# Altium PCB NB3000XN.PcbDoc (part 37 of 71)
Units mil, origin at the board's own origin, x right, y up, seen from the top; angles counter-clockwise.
Board outline 9527.56 x 6929.77 mil, 6 copper layers (Top Layer, GND+SHIELD, MidLayer1, MidLayer2, P2 - 3V3+5V0, Bottom Layer), stack 62.375 mil thick; 832 components, 1027 nets, 4655 pads, 4981 vias.
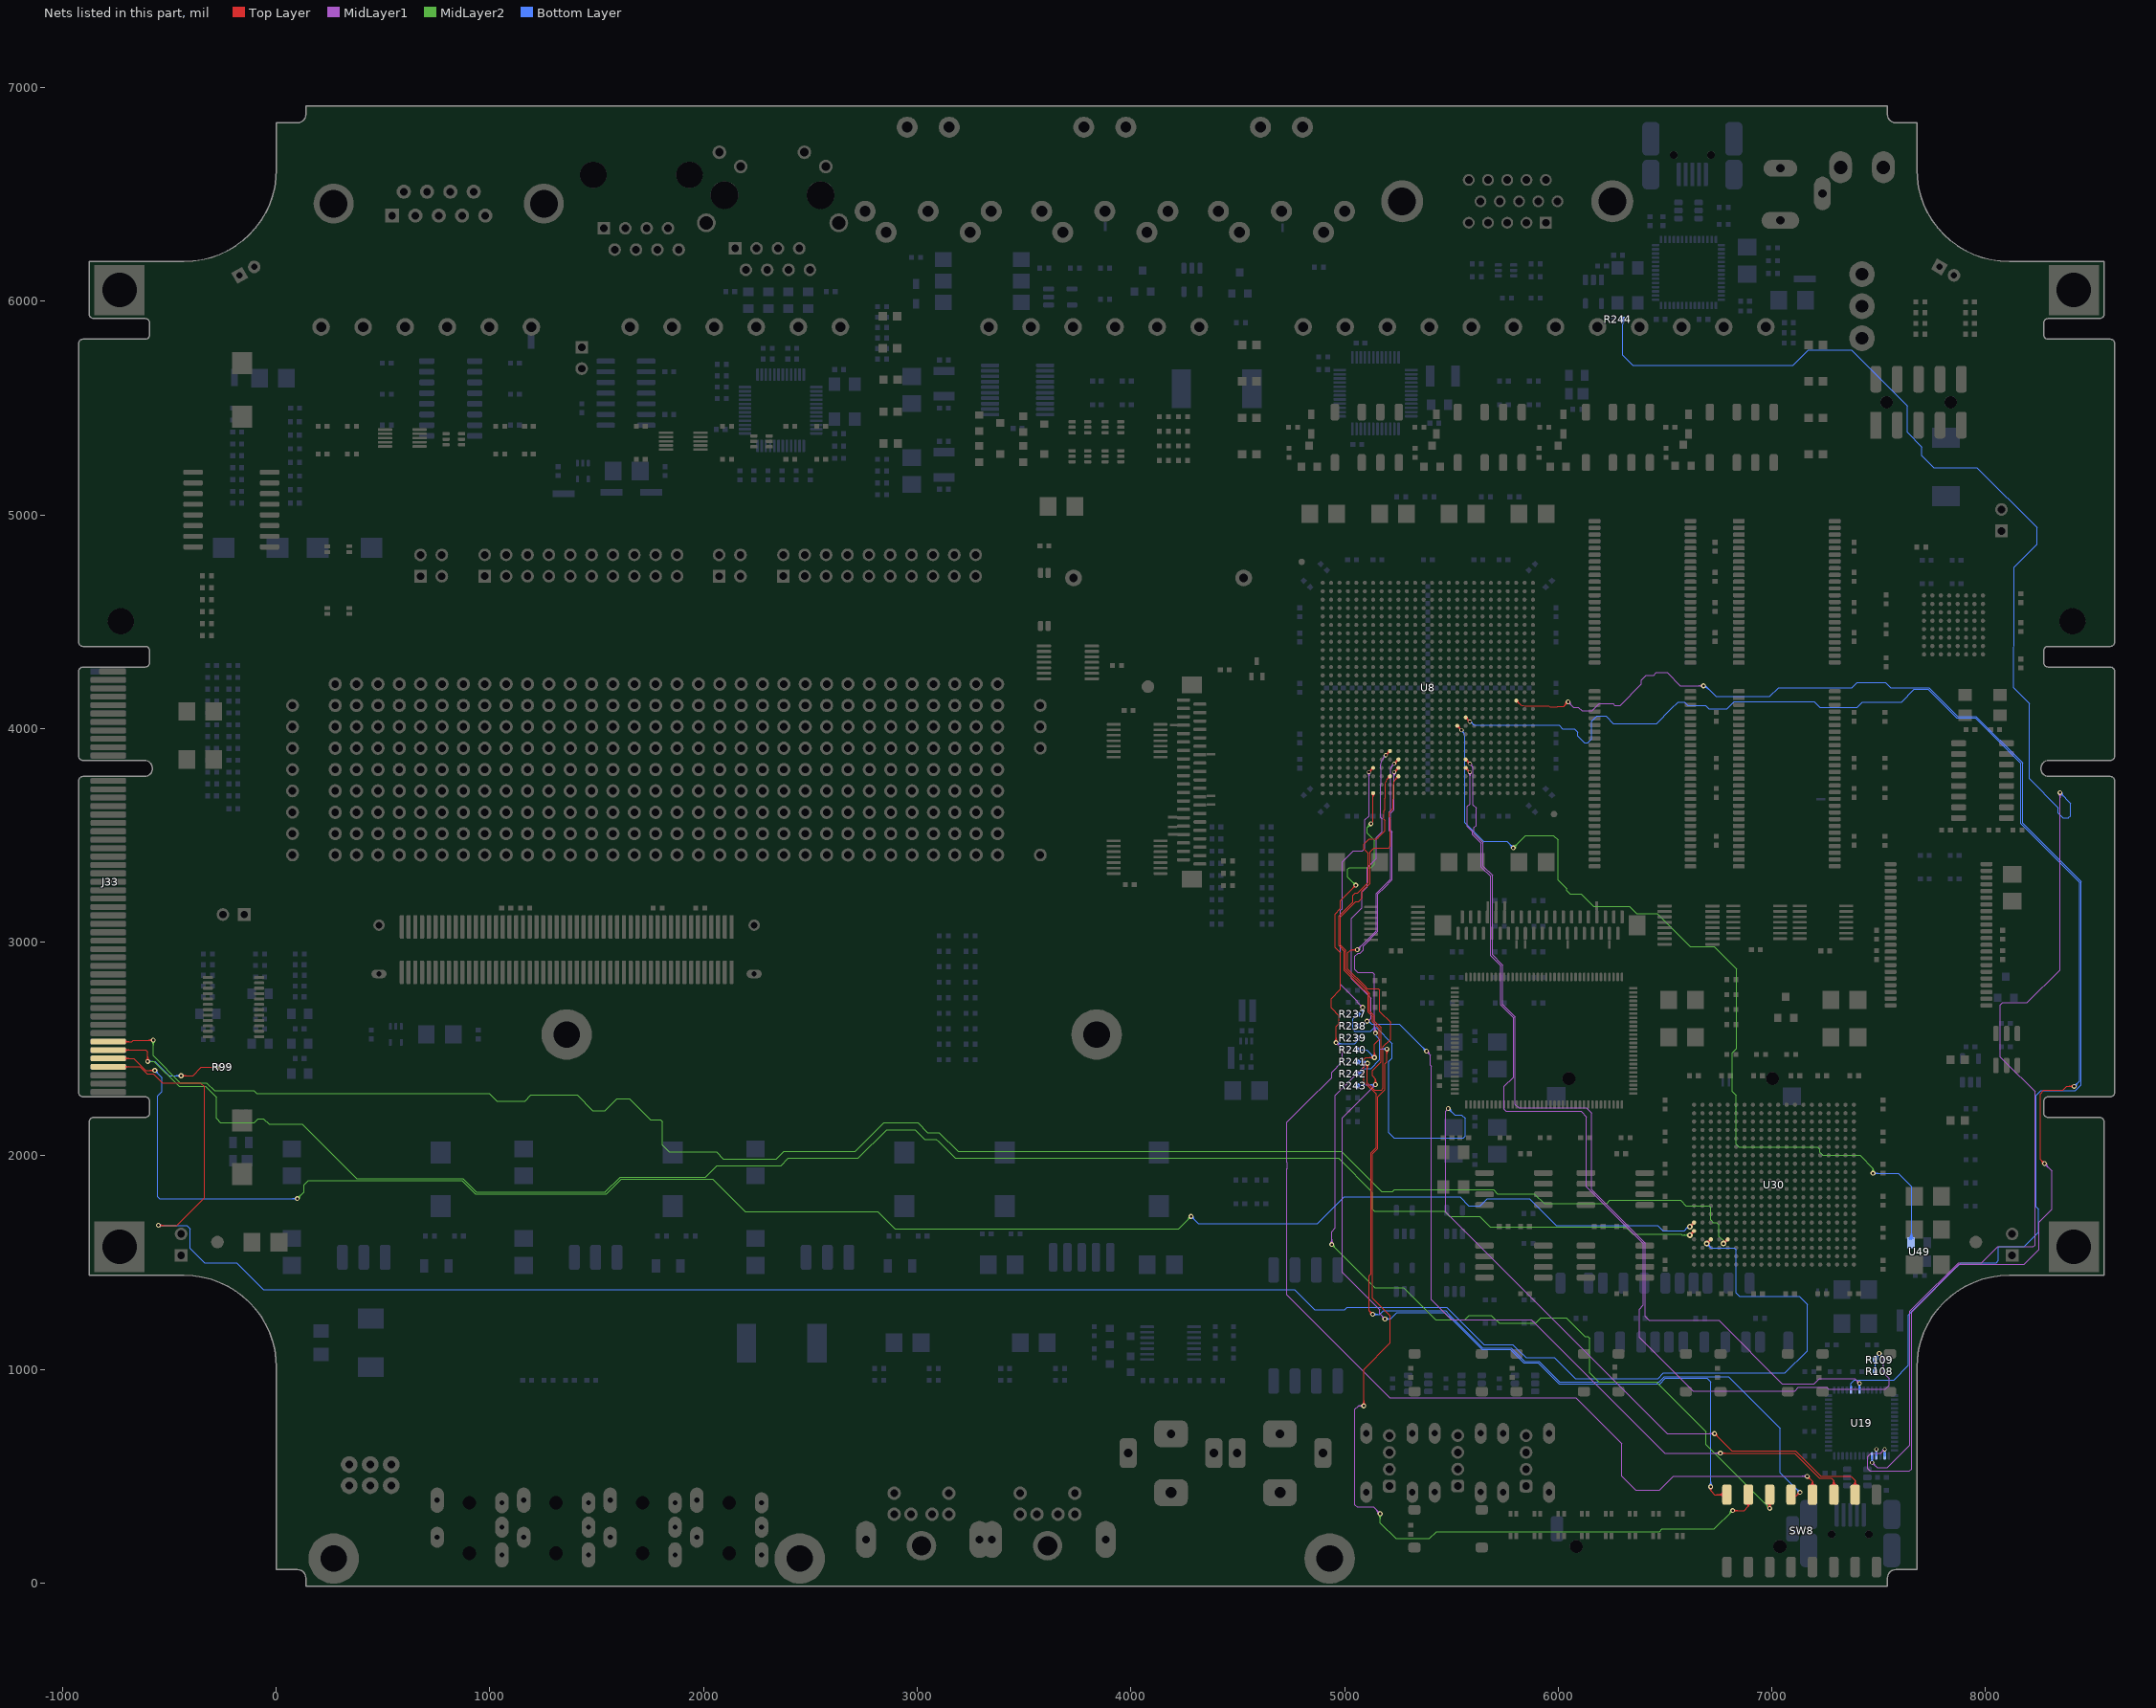
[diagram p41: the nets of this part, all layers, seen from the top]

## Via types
v1: diameter 23, hole 11.81, Top Layer to Bottom Layer, 3672 vias
v2: diameter 26, hole 11.81, Top Layer to Bottom Layer, 461 vias
v3: diameter 19, hole 11.81, Top Layer to Bottom Layer, tented both sides, 396 vias
v4: diameter 23.62, hole 11.81, Top Layer to Bottom Layer, 288 vias
v5: diameter 20, hole 11.81, Top Layer to Bottom Layer, 91 vias
v6: diameter 23, hole 11.81, Top Layer to Bottom Layer, tented both sides, 50 vias
v7: diameter 31, hole 11.81, Top Layer to Bottom Layer, 15 vias
v8: diameter 27.56, hole 11.81, Top Layer to Bottom Layer, tented both sides, 4 vias
v9: diameter 29, hole 11.81, Top Layer to Bottom Layer, 3 vias
v10: diameter 21, hole 11.81, Top Layer to Bottom Layer, 1 vias

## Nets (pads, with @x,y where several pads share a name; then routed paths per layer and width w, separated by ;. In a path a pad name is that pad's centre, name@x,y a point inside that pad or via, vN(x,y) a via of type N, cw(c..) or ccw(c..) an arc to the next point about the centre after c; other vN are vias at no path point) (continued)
DBUSB.READY: U8.R24 U19.33 | length 6898
  Top Layer w4: U8.R24@5803.39,4123.6 cw(c5803.39,4105.88) 5815.92,4118.41 ; U8.R24@5810.73,4130.94 ccw(c5828.45,4130.94) 5815.92,4118.41 ; v1@6036.69,4125.04 cw(c6013.76,4125.04) 6029.97,4108.82 cw(c6046.19,4092.61) v1@6046.19,4115.54 ; v1@6037.01,4125.04 v1(6046.19,4125.04) 6026,4104.85 5997.48,4104.85 5994.33,4101.71 5960.72,4101.71 5955.35,4107.08 5924.74,4107.08 5920,4107.08 5910,4107.08 5843.27,4107.08 cw(c5843.27,4145.76) 5815.92,4118.41 ; v1@6040.69,4125.04 cw(c6027.41,4125.04) 6036.8,4115.65 cw(c6046.19,4106.26) v1@6046.19,4119.54
  MidLayer1 w4: v1@6046.19,4115.54 cw(c6046.19,4092.61) 6062.41,4108.82 cw(c6078.63,4125.04) v1@6055.69,4125.04 ; v1@6046.19,4119.54 cw(c6046.19,4106.26) 6055.58,4115.65 cw(c6064.97,4125.04) v1@6051.69,4125.04 ; v1(6046.19,4125.04) 6071.23,4100 6095,4100 6111.63,4083.37 6159.23,4083.37 6192.56,4116.71 6256.86,4116.71 6265.19,4108.37 6290.19,4108.37 6390.19,4208.37 6390.19,4228.02 6412.21,4250.04 6447.67,4250.04 6459.34,4261.71 6509.52,4261.71 6571.19,4200.04 v1(6680.19,4200.04) ; v1@6673.47,4193.32 ccw(c6657.26,4177.11) 6657.26,4200.04 ccw(c6657.26,4222.98) v1@6673.47,4206.76 ; v1@6676.3,4196.15 ccw(c6666.91,4186.76) 6666.91,4200.04 ccw(c6666.91,4213.32) v1@6676.3,4203.93
  Bottom Layer w4: v1@6680.19,4190.54 cw(c6680.19,4146.68) 6711.2,4177.69 ; v1@6680.19,4194.54 cw(c6680.19,4160.34) 6704.37,4184.52 ; v1@6680.19,4198.54 cw(c6680.19,4174) 6697.55,4191.35 ; v1(6680.19,4200.04) 6688.86,4200.04 6738.86,4150.04 6990.19,4150.04 7032.19,4192.04 7374.19,4192.04 7398.52,4216.37 7430,4216.37 7444.19,4216.37 7532.35,4216.37 7557.02,4191.71 7575,4191.71 7734.84,4191.71 7868.84,4057.71 7955.15,4057.71 8173.52,3839.34 8173.52,3557.79 8448,3283.31 8448,2333.25 8420.68,2305.94 8260.38,2305.94 8238,2283.56 8238,1760.5 8248.36,1750.14 ; U19.33@7367.96,918.09 ccw(c7361.13,924.92) 7370.79,924.92 ccw(c7380.44,924.92) U19.33@7373.62,918.09 ; U19.33@7370.79,904.33 7370.79,935.66 7386.84,951.71 7571.71,951.71 7640,1020 7640,1255.2 7843.17,1458.37 ; 7843.37,1458.37 7885.37,1500.37 8050.37,1500.37 8060,1510 8060,1570 8065,1575 8180,1575 8248.36,1643.36 8248.36,1750.14 ; 8239.19,1759.31 8248.36,1750.14
DBUSB.RESET_N: U8.V17 U49.3 | length 4668.6
  Top Layer w4: U8.V17@5527.8,4005.33 cw(c5527.8,3987.23) 5540.6,4000.03 cw(c5553.4,4012.83) U8.V17@5535.3,4012.83 ; U8.V17@5527.8,4005.49 cw(c5527.8,3987.77) 5540.33,4000.3 cw(c5552.86,4012.83) U8.V17@5535.14,4012.83 ; U8.V17@5527.8,4012.83 v3(5547.48,3993.15) ; 5534.68,4005.95 cw(c5521.87,3993.15) 5539.98,3993.15 ccw(c5521.87,3993.15) 5534.68,4005.95 ; 5534.68,4005.95 ccw(c5547.48,4018.76) 5547.48,4000.65 cw(c5547.48,4018.76) 5534.68,4005.95
  MidLayer2 w4: v1(5790.19,3441.71) 5848.52,3500.04 5978.17,3500.04 5998.86,3479.35 5998.86,3290.95 6012.62,3277.19 6012.71,3277.19 6040.19,3249.71 6040.19,3241.71 6056.86,3225.04 6106.86,3225.04 6165.19,3166.71 6333.52,3166.71 6366.86,3133.37 6462.52,3133.37 6616.86,2979.04 6729.84,2979.04 6835.52,2873.35 6835.52,2503.71 6815.19,2483.37 6815.19,2300.37 6832.19,2283.37 6832.19,2099.96 ; v1@5790.19,3447.21 ccw(c5790.19,3460.49) 5799.58,3451.1 ccw(c5808.97,3441.71) v1@5795.69,3441.71 ; v1@5790.19,3451.21 ccw(c5790.19,3474.14) 5806.41,3457.93 ccw(c5822.63,3441.71) v1@5799.69,3441.71 ; 6832.15,2100 6832.19,2099.96 ; v1@7467.01,1925.62 ccw(c7452.8,1940.71) 7473.52,1940.71 ; v1@7469.75,1922.71 ccw(c7461.53,1931.44) 7473.52,1931.44 ccw(c7485.52,1931.44) v1@7477.3,1922.71 ; v1(7473.52,1918.71) 7473.52,1940.71 ; v1@7480.04,1925.62 cw(c7494.25,1940.71) 7473.52,1940.71 ; 6832.19,2099.96 6833.52,2098.63 6833.52,2053.98 6846.02,2041.48 7214.72,2041.48 7225.85,2030.35 7225.85,2015.98 7238.35,2003.48 7338.89,2003.48 7340,2002.37 7411.86,2002.37 7473.52,1940.71
  Bottom Layer w4: v3@5546.18,3985.76 cw(c5543.03,3967.93) 5557.87,3978.32 cw(c5572.7,3988.7) v3@5554.87,3991.85 ; 5557.9,3978.29 cw(c5529.86,3960.64) 5562.99,3960.47 5562.99,3876.1 5562.99,3670 5562.99,3660 5562.99,3558.91 5573.65,3548.24 5650.19,3471.71 5760.19,3471.71 v1(5790.19,3441.71) ; v1@5780.69,3441.71 ccw(c5757.76,3441.71) 5773.97,3457.93 ccw(c5790.19,3474.14) v1@5790.19,3451.21 ; v1@5784.69,3441.71 ccw(c5771.41,3441.71) 5780.8,3451.1 ccw(c5790.19,3460.49) v1@5790.19,3447.21 ; v1(7473.52,1918.71) 7591.29,1918.71 7655,1855 U49.3@7655,1607 ; v1@7477.41,1914.82 cw(c7486.8,1905.43) 7486.8,1918.71 cw(c7486.8,1931.99) v1@7477.41,1922.6 ; v1@7480.24,1911.99 cw(c7496.46,1895.77) 7496.46,1918.71 cw(c7496.46,1941.64) v1@7480.24,1925.43 ; U49.3@7641.03,1613.28 ccw(c7607.31,1647) 7655,1647 ; U49.3@7643.86,1610.45 ccw(c7616.97,1637.34) 7655,1637.34 ; U49.3@7646.69,1607.62 ccw(c7626.63,1627.69) 7655,1627.69 ; 7655,1623.56 ccw(c7673.54,1623.56) U49.3@7660.43,1610.45 ; 7655,1633.22 ccw(c7683.2,1633.22) U49.3@7663.26,1613.28
DBUSB.SLOE: U8.AB18 U19.35 | length 4508.8
  Top Layer w4: U8.AB18@5567.17,3847.85 cw(c5567.17,3829.75) 5579.97,3842.55 cw(c5592.77,3855.35) U8.AB18@5574.67,3855.35 ; U8.AB18@5567.17,3848.01 cw(c5567.17,3830.29) 5579.7,3842.82 cw(c5592.23,3855.35) U8.AB18@5574.51,3855.35 ; U8.AB18@5567.17,3855.35 v3(5586.85,3835.67) ; 5574.05,3848.47 cw(c5561.24,3835.67) 5579.35,3835.67 ccw(c5561.24,3835.67) 5574.05,3848.47 ; 5574.05,3848.47 ccw(c5586.85,3861.28) 5586.85,3843.17 cw(c5586.85,3861.28) 5574.05,3848.47
  MidLayer1 w4: v3@5586.2,3828.2 cw(c5584.62,3810.16) 5598.49,3821.8 cw(c5612.36,3833.44) v3@5594.32,3835.02 ; 5598.24,3822.09 cw(c5588.31,3812.16) 5602.36,3812.16 5602.36,3718.62 5602.36,3670 5602.36,3660 5602.36,3642.64 5616.19,3628.81 5616.19,3545.69 5606.86,3536.35 5606.86,3508.04 5648.52,3466.37 5648.52,3356.68 5692.19,3313.02 5692.19,2940.98 5730.85,2902.32 5740.19,2892.98 5740.19,2708.37 5798.52,2650.04 5798.52,2241.71 5815.19,2225.04 6131.86,2225.04 6156.86,2200.04 6156.86,1841.71 6406.81,1591.75 6406.81,1248.19 6425,1230 6751.9,1230 7048.52,933.37 7198.52,933.37 7223.52,958.37 7387.44,958.37 v5(7410.16,935.66) ; v5@7402.16,935.66 ccw(c7382.84,935.66) 7396.5,949.32 ccw(c7410.16,962.98) v5@7410.16,943.66
  Bottom Layer w8: v5@7405.91,931.42 cw(c7395.67,921.18) 7410.16,921.18 cw(c7424.64,921.18) v5@7414.4,931.42 ; U19.35@7410.16,904.33 v5(7410.16,935.66)
DBUSB.VBUS: R108.1 R109.1 U8.AC18 | length 5262
  Top Layer w4: U8.AC18@5567.17,3808.48 cw(c5567.17,3790.38) 5579.97,3803.18 cw(c5592.77,3815.98) U8.AC18@5574.67,3815.98 ; U8.AC18@5567.17,3808.64 cw(c5567.17,3790.92) 5579.7,3803.45 cw(c5592.23,3815.98) U8.AC18@5574.51,3815.98 ; U8.AC18@5567.17,3815.98 v3(5586.85,3796.3) ; 5574.05,3809.1 cw(c5561.24,3796.3) 5579.35,3796.3 ccw(c5561.24,3796.3) 5574.05,3809.1 ; 5574.05,3809.1 ccw(c5586.85,3821.91) 5586.85,3803.8 cw(c5586.85,3821.91) 5574.05,3809.1
  MidLayer1 w4: v3@5581.55,3791 cw(c5568.74,3778.19) 5586.85,3778.19 cw(c5604.96,3778.19) v3@5592.15,3791 ; v3@5581.66,3791.11 cw(c5569.12,3778.57) 5586.85,3778.57 cw(c5604.58,3778.57) v3@5592.04,3791.11 ; v3(5586.85,3796.3) 5586.85,3718.62 5586.85,3670 5586.85,3660 5586.85,3646.66 5575.19,3635 5575.19,3541.12 5598.86,3517.46 5598.86,3504.71 5612.27,3491.29 5640.19,3463.37 5640.19,3352.37 5684.19,3308.37 5684.19,2937.67 5731.86,2890 5731.86,2705.39 5790.52,2646.73 5790.52,2368.02 5747.5,2325 5747.5,2217.73 5756.86,2208.37 6106.86,2208.37 6131.86,2183.37 6131.86,1855.39 6377.04,1610.21 6398.81,1588.44 6398.81,1301.18 6380.52,1282.9 6380.52,1149.61 6630.43,899.71 7108,899.71 7125,916.71 7256.86,916.71 7265.19,908.37 7531.86,908.37 7548.52,925.04 7548.52,958.37 7523.52,983.37 7523.52,1054.04 v1(7502.52,1075.04) ; v1@7502.52,1065.54 cw(c7502.52,1042.61) 7518.74,1058.82 cw(c7534.96,1075.04) v1@7512.02,1075.04 ; v1@7502.52,1069.54 cw(c7502.52,1056.26) 7511.91,1065.65 cw(c7521.3,1075.04) v1@7508.02,1075.04
  Bottom Layer w4: R108.1@7477.23,997.08 ccw(c7461.32,1012.99) 7483.82,1012.99 ccw(c7506.32,1012.99) R108.1@7490.41,997.08 ; R109.1@7477.23,1037.92 cw(c7461.32,1022.01) 7483.82,1022.01 cw(c7506.32,1022.01) R109.1@7490.41,1037.92 ; R108.1@7480.06,994.25 ccw(c7470.98,1003.33) 7483.82,1003.33 ccw(c7496.66,1003.33) R108.1@7487.58,994.25 ; R109.1@7480.06,1040.75 cw(c7470.98,1031.67) 7483.82,1031.67 cw(c7496.66,1031.67) R109.1@7487.58,1040.75 ; R108.1@7483.82,990 R109.1@7483.82,1041.71 ; R109.1@7483.82,1045 R109.1@7483.82,1041.71 ; R109.1@7485.14,1045.57 cw(c7501.49,1046.51) 7489.91,1058.09 ; R109.1@7489.13,1045.8 cw(c7513.42,1047.2) 7496.21,1064.4 ; 7492.36,1060.54 ccw(c7486.07,1066.83) v1@7494.02,1070.8 ; R109.1@7493.12,1046.03 cw(c7525.35,1047.88) v1@7502.52,1070.71 ; 7493.7,1061.89 cw(c7502.52,1053.07) v1@7502.52,1065.54 ; 7496.28,1064.47 ccw(c7491.31,1069.44) v1@7497.6,1072.58 ; v1(7502.52,1075.04) v1@7502.52,1070.71 ; R109.1@7483.82,1041.71 7485.47,1043.35 7490.19,1048.08 7490.19,1058.37 v1@7502.52,1070.71 ; R109.1@7483.82,1054.81 ccw(c7483.82,1061.59) 7488.61,1056.8 cw(c7483.82,1061.59) R109.1@7483.82,1054.81
DBUSB.WR_N: U8.U18 U19.2 | length 7864.3
  Top Layer w4: U8.U18@5567.17,4044.7 cw(c5567.17,4026.6) 5579.97,4039.4 cw(c5592.77,4052.2) U8.U18@5574.67,4052.2 ; U8.U18@5567.17,4044.86 cw(c5567.17,4027.14) 5579.7,4039.67 cw(c5592.23,4052.2) U8.U18@5574.51,4052.2 ; U8.U18@5567.17,4052.2 v3(5586.85,4032.52) ; v1@8266.73,1964 ccw(c8243.8,1964) 8260.02,1980.22 ccw(c8276.23,1996.43) v1@8276.23,1973.5 ; v1@8270.73,1964 ccw(c8257.46,1964) 8266.85,1973.39 ccw(c8276.23,1982.78) v1@8276.23,1969.5 ; v1(8276.23,1964) 8256.86,1983.37 8256.86,2290.54 8273.31,2307 8362,2307 8380.04,2325.04 8414.96,2325.04 v1(8415,2325) ; 8391.97,2325.04 cw(c8391.97,2301.97) v1@8408.28,2318.28 ; 8392.16,2325.04 ccw(c8392.16,2347.84) v1@8408.28,2331.72 ; 8401.62,2325.04 cw(c8401.62,2311.62) v1@8411.11,2321.11 ; 8401.82,2325.04 ccw(c8401.82,2338.18) v1@8411.11,2328.89 ; 5574.05,4045.32 cw(c5561.24,4032.52) 5579.35,4032.52 ccw(c5561.24,4032.52) 5574.05,4045.32 ; 5574.05,4045.32 ccw(c5586.85,4058.13) 5586.85,4040.02 cw(c5586.85,4058.13) 5574.05,4045.32
  MidLayer1 w4: v5@7520.27,627 cw(c7500.95,627) 7514.61,613.34 cw(c7528.27,599.69) v5@7528.27,619 ; v5(7528.27,627) 7509.64,608.37 7465.19,608.37 7448.52,591.71 7448.52,536.48 7460,525 7644.38,525 7654.02,534.64 7654.02,1269.23 7876.51,1491.71 8180,1491.71 8250,1561.71 8250,1690 8310,1750 8310,1930.23 v1(8276.23,1964) v1@8276.11,1964.12 ; v1@8276.23,1954.5 cw(c8276.23,1931.56) 8292.45,1947.78 cw(c8308.67,1964) v1@8285.73,1964 ; v1@8276.23,1958.5 cw(c8276.23,1945.22) 8285.62,1954.61 cw(c8295.01,1964) v1@8281.73,1964
  Bottom Layer w4: v3@5587.5,4025.05 cw(c5589.08,4007.01) 5600.72,4020.88 cw(c5612.36,4034.75) v3@5594.32,4033.17 ; 5600.43,4021.13 ccw(c5610.36,4031.06) 5610.36,4017.01 5703.9,4017.01 5910,4017.01 5920,4017.01 5924.74,4017.01 5928.74,4017.01 5928.74,4016.71 6003.86,4016.71 6021.06,3999.5 6075.25,3999.5 6092.5,3982.25 6092.5,3963.98 6123.12,3933.37 6137.61,3933.37 6156.86,3952.61 6156.86,4033.37 6181.86,4058.37 6223.52,4058.37 6257.69,4024.21 6460.77,4024.21 6528.19,4091.63 6528.19,4091.71 6561.52,4125.04 6590.19,4125.04 6606.86,4108.37 6688.86,4108.37 6705.52,4091.71 6790,4091.71 6824.33,4126.04 7198.96,4126.04 7224.96,4100.04 7398.52,4100.04 7423.52,4125.04 7606.67,4125.04 7665,4183.37 7731.86,4183.37 7865.52,4049.71 7951.84,4049.71 8165.19,3836.36 8165.19,3554.81 8440,3280 8440,2350 v1(8415,2325) ; v1@8415,2330.5 ccw(c8415,2343.78) 8424.39,2334.39 ccw(c8433.78,2325) v1@8420.5,2325 ; v1@8415,2334.5 ccw(c8415,2357.43) 8431.22,2341.22 ccw(c8447.44,2325) v1@8424.5,2325
  Bottom Layer w8: v5@7524.03,622.76 cw(c7513.78,612.51) 7528.27,612.51 cw(c7542.75,612.51) v5@7532.51,622.76 ; U19.2@7528.27,595.67 v5(7528.27,627)
DBUSB.XTALIN: R244.1 U19.5 | length 8457.5
  MidLayer1 w4: v5@7469.21,556.34 cw(c7469.21,537.02) 7482.87,550.68 cw(c7496.53,564.34) v5@7477.21,564.34 ; v5(7469.21,564.34) 7493.55,540 7540,540 7646.02,646.02 7646.02,1272.54 7677.84,1304.35 7873.52,1500.04 7981.86,1500.04 8056.86,1575.04 8224.19,1575.04 8231.86,1582.71 8231.86,2300.04 8094.47,2437.43 8070,2461.9 8070,2706.71 8080,2716.71 8195.23,2716.71 8348.52,2870 v1(8348.52,3700.04) ; v1@8341.81,3693.32 cw(c8325.59,3677.11) 8348.52,3677.11 cw(c8371.46,3677.11) v1@8355.24,3693.32 ; v1@8344.64,3696.15 cw(c8335.25,3686.76) 8348.52,3686.76 cw(c8361.8,3686.76) v1@8352.41,3696.15
  Bottom Layer w4: R244.1@6294.59,5907.92 cw(c6278.68,5892.01) 6301.18,5892.01 cw(c6323.68,5892.01) R244.1@6307.77,5907.92 ; R244.1@6297.42,5910.75 cw(c6288.34,5901.67) 6301.18,5901.67 cw(c6314.02,5901.67) R244.1@6304.94,5910.75 ; R244.1@6301.18,5915 6301.18,5747.38 6348.52,5700.04 7098.52,5700.04 7170.48,5772 7372.36,5772 7633.75,5510.61 7633.75,5386.25 7701.98,5318.02 7701.98,5278.02 7758.88,5221.12 7960.17,5221.12 8240.69,4940.6 8240.69,4862 8135,4756.31 8135,4385 8131.86,4381.86 8131.86,4191.37 8206.52,4116.71 8206.52,3764.53 8341.06,3630 8341.06,3603.94 8362.13,3582.87 8389.69,3582.87 8390.19,3583.37 8398.52,3591.71 8399.02,3592.21 8399.02,3649.54 v1(8348.52,3700.04) ; v1@8348.52,3690.54 cw(c8348.52,3667.61) 8364.74,3683.82 cw(c8380.96,3700.04) v1@8358.02,3700.04 ; v1@8348.52,3694.54 cw(c8348.52,3681.26) 8357.91,3690.65 cw(c8367.3,3700.04) v1@8354.02,3700.04
  Bottom Layer w8: v5@7464.97,568.58 ccw(c7454.73,578.82) 7469.21,578.82 ccw(c7483.7,578.82) v5@7473.46,568.58 ; v5(7469.21,564.34) U19.5@7469.21,595.67
DBUSB.XTALOUT: U19.4 | length 54.1
  Bottom Layer w8: v5@7484.65,622.76 cw(c7474.41,612.51) 7488.9,612.51 cw(c7503.38,612.51) v5@7493.14,622.76 ; U19.4@7488.9,595.67 v5(7488.9,627)
DIAGCOMMS.DIN: J33.A46 U30.V17 | length 10672.3
  Top Layer w4: J33.A46@-785.98,2416.64 -637.72,2416.64 -605.08,2384 -575.14,2384 -533.18,2342.04 -354.79,2342.04 -335.52,2322.77 -335.52,1804.48 -464.96,1675.04 v1(-551.48,1675.04) ; J33.A46@-711.58,2411.14 cw(c-698.3,2397.86) -698.3,2416.64 cw(c-698.3,2435.42) J33.A46@-711.58,2422.14 ; J33.A46@-708.76,2408.31 cw(c-688.65,2388.2) -688.65,2416.64 cw(c-688.65,2445.08) J33.A46@-708.76,2424.97 ; v1@-547.59,1671.15 cw(c-538.2,1661.76) -538.2,1675.04 cw(c-538.2,1688.32) v1@-547.59,1678.93 ; v1@-544.76,1668.32 cw(c-528.54,1652.11) -528.54,1675.04 cw(c-528.54,1697.98) v1@-544.76,1681.76
  Top Layer w8: v2(6695.04,1589.41) U30.V17@6714.72,1609.09 ; v2@6695.04,1598.41 ccw(c6695.04,1620.14) 6710.4,1604.77 ccw(c6725.77,1589.41) v2@6704.04,1589.41 ; U30.V17@6708.88,1609.09 cw(c6694.78,1609.09) 6704.75,1599.12 cw(c6714.72,1589.15) U30.V17@6714.72,1603.25
  Bottom Layer w4: v1(-551.48,1675.04) -418.14,1675.04 -401.48,1658.37 -401.48,1566.71 -334.81,1500.04 -184.81,1500.04 -59.81,1375.04 4765.19,1375.04 4860.23,1280 5000,1280 5011.71,1291.71 5478.88,1291.71 5653.58,1117 5786.92,1117 5813.92,1090 5842.12,1061.8 5848.92,1055 5982.88,1055 6079.5,958.37 6466.84,958.37 6491.84,983.37 7062.06,983.37 7165.52,1086.84 7165.52,1304.48 7128.29,1341.71 6849.52,1341.71 6832.86,1358.37 6832.86,1560.04 6823.52,1569.37 6715.07,1569.37 v2(6695.04,1589.41) ; v1@-547.59,1671.15 cw(c-538.2,1661.76) -538.2,1675.04 cw(c-538.2,1688.32) v1@-547.59,1678.93 ; v1@-544.76,1668.32 cw(c-528.54,1652.11) -528.54,1675.04 cw(c-528.54,1697.98) v1@-544.76,1681.76 ; v2@6695.04,1578.41 cw(c6695.04,1551.85) 6713.82,1570.63 cw(c6732.6,1589.41) v2@6706.04,1589.41 ; v2@6695.04,1582.41 cw(c6695.04,1565.51) 6706.99,1577.46 cw(c6718.94,1589.41) v2@6702.04,1589.41
DIAGCOMMS.DOUT: J33.A43 U30.T17 | length 8639.2
  Top Layer w4: J33.A43@-785.98,2534.75 -675.1,2534.75 -668.14,2541.71 v1(-575.48,2541.71) ; J33.A43@-711.58,2529.25 cw(c-698.3,2515.97) -698.3,2534.75 cw(c-698.3,2553.53) J33.A43@-711.58,2540.25 ; J33.A43@-708.76,2526.42 cw(c-688.65,2506.31) -688.65,2534.75 cw(c-688.65,2563.19) J33.A43@-708.76,2543.08 ; v1@-582.19,2534.99 ccw(c-598.41,2518.77) -598.41,2541.71 ccw(c-598.41,2564.64) v1@-582.19,2548.43 ; v1@-579.36,2537.82 ccw(c-588.75,2528.43) -588.75,2541.71 ccw(c-588.75,2554.99) v1@-579.36,2545.6
  Top Layer w8: v2(6773.78,1589.41) U30.T17@6793.46,1609.09 ; v2@6773.78,1598.41 ccw(c6773.78,1620.14) 6789.14,1604.77 ccw(c6804.51,1589.41) v2@6782.78,1589.41 ; U30.T17@6787.62,1609.09 cw(c6773.52,1609.09) 6783.49,1599.12 cw(c6793.46,1589.15) U30.T17@6793.46,1603.25
  MidLayer2 w4: v1@-582.19,2534.99 cw(c-598.41,2518.77) -575.48,2518.77 cw(c-552.54,2518.77) v1@-568.76,2534.99 ; v1@-579.36,2537.82 cw(c-588.75,2528.43) -575.48,2528.43 cw(c-562.2,2528.43) v1@-571.59,2537.82 ; v1(-575.48,2541.71) -575.48,2468.14 -449.04,2341.71 -325.39,2341.71 -288.69,2305 -105,2305 -92,2292 998,2292 1033,2257 1164.63,2257 1192,2284.37 1409.31,2284.37 1481.69,2212 1539.23,2212 1595.23,2268 1653.35,2268 1751.35,2170 1798.67,2170 1808.67,2160 1808.67,2049.33 1840,2018 2059.67,2018 2091.67,1986 2341,1986 2375.81,2020.81 2710,2020.81 2844.19,2155 3002.5,2155 3048,2109.5 3102.36,2109.5 3191.05,2020.81 4986.09,2020.81 5174.19,1832.71 5225.84,1832.71 5235,1841.87 5697.34,1841.87 5716.5,1822.71 5888.88,1822.71 5934.88,1776.71 6227.56,1776.71 6242.56,1791.71 6573.52,1791.71 6598.52,1766.71 6706.86,1766.71 6715.19,1758.37 6715.19,1699.87 6726.54,1688.52 6740.91,1688.52 6753.41,1676.02 6753.41,1622.28 6773.78,1601.91 v2(6773.78,1589.41)
DIAGCOMMS.FLASH_CS_N: J33.A44 R99.1 U30.Y16 | length 9034.8
  Top Layer w4: J33.A44@-785.98,2495.38 -610.38,2495.38 -601.48,2486.48 v1(-601.48,2441.71) ; J33.A44@-711.58,2489.88 cw(c-698.3,2476.6) -698.3,2495.38 cw(c-698.3,2514.16) J33.A44@-711.58,2500.88 ; J33.A44@-708.76,2487.05 cw(c-688.65,2466.94) -688.65,2495.38 cw(c-688.65,2523.82) J33.A44@-708.76,2503.71 ; v1@-608.19,2448.43 ccw(c-624.41,2464.64) -601.48,2464.64 ccw(c-578.54,2464.64) v1@-594.76,2448.43 ; v1@-605.36,2445.6 ccw(c-614.75,2454.99) -601.48,2454.99 ccw(c-588.2,2454.99) v1@-597.59,2445.6 ; v1(-445,2375) -390,2375 -350,2415 R99.1@-271.18,2415 ; v1@-441.11,2371.11 cw(c-431.72,2361.72) -431.72,2375 cw(c-431.72,2388.28) v1@-441.11,2378.89 ; v1@-438.28,2368.28 cw(c-422.07,2352.06) -422.07,2375 cw(c-422.07,2397.93) v1@-438.28,2381.72 ; R99.1@-277.77,2408.41 ccw(c-293.68,2392.5) -293.68,2415 ccw(c-293.68,2437.5) R99.1@-277.77,2421.59 ; R99.1@-274.94,2411.24 ccw(c-284.02,2402.16) -284.02,2415 ccw(c-284.02,2427.84) R99.1@-274.94,2418.76
  Top Layer w8: v2(6616.3,1628.78) U30.Y16@6635.98,1648.46 ; v2@6616.3,1637.78 ccw(c6616.3,1659.51) 6631.66,1644.14 ccw(c6647.03,1628.78) v2@6625.3,1628.78 ; U30.Y16@6630.14,1648.46 cw(c6616.04,1648.46) 6626.01,1638.49 cw(c6635.98,1628.52) U30.Y16@6635.98,1642.62
  MidLayer2 w4: v1(-601.48,2441.71) -571.67,2441.71 -455,2325.04 -331.35,2325.04 -280,2273.69 -280,2175.13 -260.58,2155.71 -103.29,2155.71 -85,2174 -59,2174 -34,2149 121,2149 377.5,1892.5 873.81,1892.5 936.31,1830 1540,1830 ; 1541.69,1830 1540,1830 ; v2@6608.52,1621 ccw(c6589.74,1602.22) 6589.74,1628.78 ccw(c6589.74,1655.34) v2@6608.52,1636.56 ; v2@6611.35,1623.83 ccw(c6599.4,1611.88) 6599.4,1628.78 ccw(c6599.4,1645.68) v2@6611.35,1633.73 ; v2(6616.3,1628.78) 6615.19,1628.78 6580,1628.78 6575.4,1633.37 6348.52,1633.37 6315.19,1666.71 5681.98,1666.71 5631.69,1717 5492,1717 5467.29,1741.71 5140.19,1741.71 5131.86,1750.04 5131.86,1828.41 4971.46,1988.81 3177.79,1988.81 3099.36,2067.25 3089.11,2077.5 3034.74,2077.5 2989.24,2123 2857.44,2123 2723.26,1988.81 2397.1,1988.81 2362.29,1954 2064,1954 2009.71,1899.71 1609.71,1899.71 1540,1830
  Bottom Layer w4: v1(-601.48,2441.71) -568.33,2441.71 -501.63,2375 v1(-445,2375) ; v1@-597.59,2437.82 cw(c-588.2,2428.43) -588.2,2441.71 cw(c-588.2,2454.99) v1@-597.59,2445.6 ; v1@-594.76,2434.99 cw(c-578.54,2418.77) -578.54,2441.71 cw(c-578.54,2464.64) v1@-594.76,2448.43 ; v1@-451.72,2368.28 ccw(c-467.94,2352.06) -467.94,2375 ccw(c-467.94,2397.93) v1@-451.72,2381.72 ; v1@-448.89,2371.11 ccw(c-458.28,2361.72) -458.28,2375 ccw(c-458.28,2388.28) v1@-448.89,2378.89
DIAGCOMMS.SCLK: J33.A45 U30.Y15 | length 8976.6
  Top Layer w4: J33.A45@-785.98,2456.01 -665.78,2456.01 -609.81,2400.04 v1(-568.14,2400.04) ; J33.A45@-711.58,2450.51 cw(c-698.3,2437.23) -698.3,2456.01 cw(c-698.3,2474.79) J33.A45@-711.58,2461.51 ; J33.A45@-708.76,2447.68 cw(c-688.65,2427.57) -688.65,2456.01 cw(c-688.65,2484.45) J33.A45@-708.76,2464.34 ; v1@-574.86,2393.32 ccw(c-591.08,2377.11) -591.08,2400.04 ccw(c-591.08,2422.98) v1@-574.86,2406.76 ; v1@-572.03,2396.15 ccw(c-581.42,2386.76) -581.42,2400.04 ccw(c-581.42,2413.32) v1@-572.03,2403.93
  Top Layer w8: v2(6616.3,1668.15) U30.Y15@6635.98,1687.83 ; v2@6616.3,1677.15 ccw(c6616.3,1698.88) 6631.66,1683.51 ccw(c6647.03,1668.15) v2@6625.3,1668.15 ; U30.Y15@6630.14,1687.83 cw(c6616.04,1687.83) 6626.01,1677.86 cw(c6635.98,1667.89) U30.Y15@6635.98,1681.99
  MidLayer2 w4: v1(98.52,1800.04) 130.12,1831.64 130.12,1865.12 149.5,1884.5 870.5,1884.5 933,1822 1545,1822 1614.71,1891.71 2043.29,1891.71 2195,1740 2815,1740 2897,1658 4223.15,1658 v1(4281.86,1716.71) ; v1@98.52,1805.54 ccw(c98.52,1818.82) 107.91,1809.43 ccw(c117.3,1800.04) v1@104.02,1800.04 ; v1@98.52,1809.54 ccw(c98.52,1832.48) 114.74,1816.26 ccw(c130.96,1800.04) v1@108.02,1800.04 ; v1@4272.36,1716.71 cw(c4249.42,1716.71) 4265.64,1700.49 cw(c4281.86,1684.27) v1@4281.86,1707.21 ; v1@4276.36,1716.71 cw(c4263.08,1716.71) 4272.47,1707.32 cw(c4281.86,1697.93) v1@4281.86,1711.21
  Bottom Layer w4: v1@-568.14,2390.54 cw(c-568.14,2367.61) -551.93,2383.82 cw(c-535.71,2400.04) v1@-558.64,2400.04 ; v1@-568.14,2394.54 cw(c-568.14,2381.26) -558.75,2390.65 cw(c-549.36,2400.04) v1@-562.64,2400.04 ; v1(-568.14,2400.04) -535,2366.9 -535,2300 -555,2280 -555,1809 -546.04,1800.04 v1(98.52,1800.04) ; v1@91.81,1793.32 ccw(c75.59,1777.11) 75.59,1800.04 ccw(c75.59,1822.98) v1@91.81,1806.76 ; v1@94.64,1796.15 ccw(c85.25,1786.76) 85.25,1800.04 ccw(c85.25,1813.32) v1@94.64,1803.93 ; v1@4281.86,1707.21 cw(c4281.86,1684.27) 4298.07,1700.49 cw(c4314.29,1716.71) v1@4291.36,1716.71 ; v1@4281.86,1711.21 cw(c4281.86,1697.93) 4291.25,1707.32 cw(c4300.64,1716.71) v1@4287.36,1716.71 ; v1(4281.86,1716.71) 4298.7,1699.86 4314.86,1683.71 4873.86,1683.71 4998.52,1808.37 5540.35,1808.37 5582.02,1766.71 5634.84,1766.71 5668.17,1800.04 5864.96,1800.04 5989.96,1675.04 6465.19,1675.04 6490.19,1650.04 6590.19,1650.04 6606.86,1666.71 6615.19,1666.71 6615.19,1668.15 v2(6616.3,1668.15) ; 6592.46,1652.31 cw(c6613.97,1630.8) v2@6615.86,1661.16 ; 6598.73,1658.58 cw(c6614.71,1642.6) v2@6616.11,1665.16 ; 6603.18,1663.03 ccw(c6598.06,1668.15) v2@6605.3,1668.15
DIPSW.D0: R243.1 SW8.16 U8.AD10 | length 6020.4
  Top Layer w4: v1@5138.47,2340.09 ccw(c5122.26,2356.31) 5145.19,2356.31 ccw(c5168.13,2356.31) v1@5151.91,2340.09 ; v1@5141.3,2337.26 ccw(c5131.91,2346.65) 5145.19,2346.65 ccw(c5158.47,2346.65) v1@5149.08,2337.26 ; v1(5145.19,2333.37) 5145.19,2359.81 5130,2375 5130,2400 5170.5,2440.5 5170.5,2600.34 5139.69,2631.15 5139.69,2655.58 5118.5,2676.77 5118.5,2760.11 5087.73,2790.87 5087.63,2790.87 5006.52,2871.98 5006.52,2961.33 4981.52,2986.33 4981.52,3118.75 5052.78,3190 5066.86,3190 5081.86,3205 5081.86,3238.71 5118.86,3275.71 5118.86,3423.37 5137.19,3441.71 5206.71,3441.71 5214.02,3449.02 5214.02,3580.48 5209.02,3585.48 5209.02,3606.6 5228.34,3625.92 5228.34,3660 5228.34,3670 5228.34,3736.73 ; v1@6708.13,443.79 cw(c6699.44,432.29) 6713.86,432.29 ; v1(6713.86,451.37) 6713.86,432.29 ; v1@6719.58,443.79 ccw(c6728.27,432.29) 6713.86,432.29 ; SW8.16@6775.69,399.98 ccw(c6741.13,365.42) 6741.13,414.29 ccw(c6741.12,463.17) SW8.16@6775.69,428.61 ; SW8.16@6778.51,402.81 ccw(c6750.78,375.08) 6750.78,414.29 ccw(c6750.78,453.51) SW8.16@6778.51,425.78 ; SW8.16@6781.34,405.63 ccw(c6760.44,384.73) 6760.44,414.29 ccw(c6760.44,443.85) SW8.16@6781.34,422.95 ; SW8.16@6790,414.29 6731.86,414.29 6713.86,432.29 ; 5228.34,3736.73 cw(c5267.02,3736.73) 5239.67,3764.08 ; 5228.34,3736.73 cw(c5267.02,3736.73) 5239.67,3764.08 ; 5239.67,3764.08 cw(c5252.2,3751.55) 5252.2,3769.27 ccw(c5252.2,3751.55) 5239.67,3764.08 ; 5239.67,3764.08 ccw(c5227.14,3776.61) 5244.86,3776.61 cw(c5227.14,3776.61) 5239.67,3764.08
  MidLayer1 w4: v1@5135.69,2333.37 cw(c5112.76,2333.37) 5128.97,2317.16 cw(c5145.19,2300.94) v1@5145.19,2323.87 ; v1@5139.69,2333.37 cw(c5126.41,2333.37) 5135.8,2323.99 cw(c5145.19,2314.6) v1@5145.19,2327.87 ; v1(5145.19,2333.37) 4990.19,2178.37 4990.19,1454.81 5164.19,1280.81 5164.19,1261.37 v1(5189.19,1236.37) ; v1@5179.69,1236.37 ccw(c5156.76,1236.37) 5172.97,1252.59 ccw(c5189.19,1268.81) v1@5189.19,1245.87 ; v1@5183.69,1236.37 ccw(c5170.41,1236.37) 5179.8,1245.76 ccw(c5189.19,1255.15) v1@5189.19,1241.87
  Bottom Layer w4: R243.1@5061.18,2327.73 5061.18,2333.37 v1(5145.19,2333.37) ; R243.1@5062.11,2327.29 cw(c5076.81,2312.59) 5076.81,2333.37 ; R243.1@5064.94,2324.46 cw(c5086.47,2302.93) 5086.47,2333.37 ; R243.1@5067.77,2321.63 cw(c5096.13,2293.27) 5096.13,2333.37 ; v1@5138.47,2326.66 ccw(c5122.26,2310.44) 5122.26,2333.37 ccw(c5122.26,2356.31) v1@5138.47,2340.09 ; v1@5141.3,2329.49 ccw(c5131.91,2320.1) 5131.91,2333.37 ccw(c5131.91,2346.65) v1@5141.3,2337.26 ; v1(5189.19,1236.37) 5215,1236.37 5246,1267.37 5469.27,1267.37 5500.27,1236.37 5643.64,1093 5776.98,1093 5838.98,1031 5906.63,1031 6003.92,933.71 6476.11,933.71 6501.45,959.04 6695.96,959.04 6713.86,941.14 v1(6713.86,451.37) ; v1@5193.08,1232.49 cw(c5202.47,1223.1) 5202.47,1236.37 cw(c5202.47,1249.65) v1@5193.08,1240.26 ; v1@5195.91,1229.66 cw(c5212.13,1213.44) 5212.13,1236.37 cw(c5212.13,1259.31) v1@5195.91,1243.09 ; v1@6707.14,458.09 ccw(c6690.92,474.31) 6713.86,474.31 ccw(c6736.79,474.31) v1@6720.57,458.09 ; v1@6709.97,455.26 ccw(c6700.58,464.65) 6713.86,464.65 ccw(c6727.14,464.65) v1@6717.75,455.26
DIPSW.D1: R242.1 SW8.15 U8.AC10 | length 6955.3
  Top Layer w4: v4@5083.06,836.94 ccw(c5066.31,853.69) 5090,853.69 ccw(c5113.69,853.69) v4@5096.94,836.94 ; v4@5085.89,834.11 ccw(c5075.97,844.03) 5090,844.03 ccw(c5104.03,844.03) v4@5094.11,834.11 ; v4(5090,830) 5090,1000 5214.69,1124.69 5214.69,1250.54 5201.08,1264.15 5130.52,1334.71 5130.52,1433.37 5131.86,1434.71 5131.86,2010.73 5156,2034.87 5156,2275.81 5190.19,2310 5190.19,2431 5198.52,2439.34 v1(5198.52,2500.04) ; v1@5191.81,2493.32 cw(c5175.59,2477.11) 5198.52,2477.11 cw(c5221.46,2477.11) v1@5205.24,2493.32 ; v1@5194.64,2496.15 cw(c5185.25,2486.76) 5198.52,2486.76 cw(c5211.8,2486.76) v1@5202.41,2496.15 ; v3(5232.52,3796.3) U8.AC10@5252.2,3815.98 ; U8.AC10@5244.7,3815.98 cw(c5226.6,3815.98) 5239.4,3803.18 cw(c5252.2,3790.38) U8.AC10@5252.2,3808.48 ; U8.AC10@5244.86,3815.98 cw(c5227.14,3815.98) 5239.67,3803.45 cw(c5252.2,3790.92) U8.AC10@5252.2,3808.64 ; v1(6816.86,340.04) 6871.67,340.04 6890,358.37 ; v1@6820.75,336.15 cw(c6830.14,326.76) 6830.14,340.04 cw(c6830.14,353.32) v1@6820.75,343.93 ; v1@6823.57,333.32 cw(c6839.79,317.11) 6839.79,340.04 cw(c6839.79,362.98) v1@6823.57,346.76 ; SW8.15@6882.35,369.76 cw(c6877.7,358.38) 6890,358.38 ; SW8.15@6883.86,373.46 cw(c6880.13,364.33) 6890,364.33 cw(c6899.87,364.33) SW8.15@6896.14,373.46 ; SW8.15@6890,414.29 6890,358.37 ; SW8.15@6897.65,369.76 ccw(c6902.3,358.38) 6890,358.38 ; 5245.32,3809.1 ccw(c5258.13,3796.3) 5240.02,3796.3 cw(c5258.13,3796.3) 5245.32,3809.1 ; 5245.32,3809.1 cw(c5232.52,3821.91) 5232.52,3803.8 ccw(c5232.52,3821.91) 5245.32,3809.1
  MidLayer1 w4: v4@5083.06,823.06 ccw(c5066.31,806.31) 5066.31,830 ccw(c5066.31,853.69) v4@5083.06,836.94 ; v4@5085.89,825.89 ccw(c5075.97,815.97) 5075.97,830 ccw(c5075.97,844.03) v4@5085.89,834.11 ; v4(5090,830) 5065,830 5048.19,813.19 5048.19,366.81 5058.27,356.73 5135,356.73 v4(5166.73,325) ; v1@5138.28,2581.72 ccw(c5133.68,2586.32) 5140.19,2586.32 ; 5140.19,2590.23 ccw(c5160.23,2590.23) v1@5146.06,2576.06 ; 5140.19,2599.89 ccw(c5169.89,2599.89) v1@5148.89,2578.89 ; 5140.19,2609.55 ccw(c5179.55,2609.55) v1@5151.72,2581.72 ; v1@5146.78,2576.78 5140.19,2583.37 5140.19,2850.04 5131.86,2858.37 5061.63,2858.37 5048.69,2871.31 5048.69,2933.69 5062.71,2947.71 5072.71,2947.71 5089.25,2964.25 5089.25,2982.94 5156.52,3050.21 5156.52,3225.71 5189.19,3258.37 5223.86,3293.04 5223.86,3517.35 5216.86,3524.35 5216.86,3605 5232.52,3620.66 5232.52,3660 5232.52,3670 5232.52,3718.62 v3(5232.52,3796.3) ; v4@5156.92,325 ccw(c5133.23,325) 5149.98,341.75 ccw(c5166.73,358.5) v4@5166.73,334.81 ; v4@5160.92,325 ccw(c5146.89,325) 5156.81,334.92 ccw(c5166.73,344.84) v4@5166.73,330.81 ; v3@5227.33,3791.11 cw(c5214.79,3778.57) 5232.52,3778.57 cw(c5250.25,3778.57) v3@5237.71,3791.11 ; 5232.52,3778.19 cw(c5250.63,3778.19) 5237.82,3791 ccw(c5250.63,3778.19) 5232.52,3778.19 ; 5232.52,3778.19 ccw(c5214.41,3778.19) 5227.22,3791 cw(c5214.41,3778.19) 5232.52,3778.19
  MidLayer2 w4: v4@5159.79,318.06 cw(c5143.04,301.31) 5166.73,301.31 cw(c5190.41,301.31) v4@5173.67,318.06 ; v4@5162.62,320.89 cw(c5152.7,310.97) 5166.73,310.97 cw(c5180.76,310.97) v4@5170.84,320.89 ; v4(5166.73,325) 5166.73,281.84 5240.19,208.37 5398.52,208.37 5431.86,241.71 6473.52,241.71 6485.89,254.08 6730.89,254.08 v1(6816.86,340.04) ; v1@6807.36,340.04 cw(c6784.42,340.04) 6800.64,323.82 cw(c6816.86,307.61) v1@6816.86,330.54 ; v1@6811.36,340.04 cw(c6798.08,340.04) 6807.47,330.65 cw(c6816.86,321.26) v1@6816.86,334.54
  Bottom Layer w4: R242.1@5061.12,2381.45 ccw(c5061.63,2405.49) 5078.63,2388.48 ; R242.1@5061.18,2383.64 5073.79,2383.64 5098.52,2408.37 ; R242.1@5061.21,2385.45 ccw(c5061.91,2418.47) 5085.26,2395.11 ; R242.1@5061.29,2389.45 ccw(c5062.18,2431.46) 5091.89,2401.74 ; R242.1@5061.38,2393.44 ccw(c5062.45,2444.44) 5098.52,2408.37 ; v1@5148.52,2575 5148.52,2560.04 5165.19,2543.37 5165.19,2500.04 ; v1@5191.81,2493.32 ccw(c5175.59,2477.11) 5175.59,2500.04 ccw(c5175.59,2522.98) v1@5191.81,2506.76 ; v1@5194.64,2496.15 ccw(c5185.25,2486.76) 5185.25,2500.04 ccw(c5185.25,2513.32) v1@5194.64,2503.93 ; v1(5198.52,2500.04) 5165.19,2500.04 ; 5098.52,2408.37 5123.52,2408.37 5165.19,2450.04 5165.19,2500.04
  other v1: 5145,2575
DIPSW.D2: R241.1 SW8.14 U8.AB10 | length 6545.4
  Top Layer w4: v1@5053.28,2958.28 ccw(c5037.06,2942.06) 5037.06,2965 ccw(c5037.06,2987.93) v1@5053.28,2971.72 ; v1@5056.11,2961.11 ccw(c5046.72,2951.72) 5046.72,2965 ccw(c5046.72,2978.28) v1@5056.11,2968.89 ; v1(5060,2965) 5030,2965 5014.52,2949.52 5014.52,2875.29 5092.57,2797.25 5092.67,2797.25 5106.55,2783.37 5156.86,2783.37 5165.19,2775.04 5165.19,2675.04 5215.19,2625.04 5215.19,2545.19 5181.02,2511.02 5181.02,2316.02 5173.37,2308.37 5140.19,2308.37 5107,2341.56 5107,2432.85 v1(5107.52,2433.37) ; v1@5100.81,2426.66 cw(c5085.85,2411.71) 5107,2411.71 ; v1@5103.64,2429.49 cw(c5095.51,2421.36) 5107,2421.36 ; 5107,2409.17 cw(c5131.72,2409.17) v1@5114.24,2426.66 ; 5107,2418.83 cw(c5122.07,2418.83) v1@5111.41,2429.49 ; v3(5232.52,3835.67) U8.AB10@5252.2,3855.35 ; U8.AB10@5244.7,3855.35 cw(c5226.6,3855.35) 5239.4,3842.55 cw(c5252.2,3829.75) U8.AB10@5252.2,3847.85 ; U8.AB10@5244.86,3855.35 cw(c5227.14,3855.35) 5239.67,3842.82 cw(c5252.2,3830.29) U8.AB10@5252.2,3848.01 ; SW8.14@6983.36,369.38 cw(c6980.11,360.04) v1@6990,360.04 ; v1@6983.47,356.76 ccw(c6967.71,372.52) SW8.14@6990,372.52 ; SW8.14@6984.67,373.16 cw(c6982.07,365.67) 6990,365.67 cw(c6997.93,365.67) SW8.14@6995.33,373.16 ; v1@6986.3,353.93 ccw(c6977.37,362.86) 6990,362.86 ; 6990,363.78 ccw(c7003.93,363.78) v1@6994.08,353.93 ; SW8.14@6990,373.43 ccw(c7013.58,373.43) v1@6996.91,356.76 ; SW8.14@6990,414.29 v1@6990,360.04 ; v1(6990.19,350.04) 6981.86,358.37 6988.33,358.37 v1@6990,360.04 ; SW8.14@6996.64,369.38 ccw(c6999.89,360.04) v1@6990,360.04 ; 5245.32,3848.47 cw(c5232.52,3861.28) 5232.52,3843.17 ccw(c5232.52,3861.28) 5245.32,3848.47 ; 5245.32,3848.47 ccw(c5258.13,3835.67) 5240.02,3835.67 cw(c5258.13,3835.67) 5245.32,3848.47
  MidLayer1 w4: v1@4933.47,1591.76 ccw(c4917.26,1607.98) 4940.19,1607.98 ccw(c4963.13,1607.98) v1@4946.91,1591.76 ; v1@4936.3,1588.93 ccw(c4926.91,1598.32) 4940.19,1598.32 ccw(c4953.47,1598.32) v1@4944.08,1588.93 ; v1(4940.19,1585.04) 4940.19,1645 4957.19,1662 4957.19,2283.04 5075.26,2401.11 v1(5107.52,2433.37) ; v1(5060,2965) 5148.52,3053.52 5148.52,3229.02 5215.86,3296.35 5215.86,3514.04 5208.86,3521.04 5208.86,3608.31 5217.01,3616.47 5217.01,3660 5217.01,3670 5217.01,3718.62 5217.01,3812.16 ; v1@5060,2970.5 ccw(c5060,2983.78) 5069.39,2974.39 ccw(c5078.78,2965) v1@5065.5,2965 ; v1@5060,2974.5 ccw(c5060,2997.43) 5076.22,2981.22 ccw(c5092.43,2965) v1@5069.5,2965 ; v1@5098.02,2433.37 cw(c5075.09,2433.37) 5091.31,2417.16 cw(c5107.52,2400.94) v1@5107.52,2423.87 ; v1@5102.02,2433.37 cw(c5088.75,2433.37) 5098.14,2423.99 cw(c5107.52,2414.6) v1@5107.52,2427.87 ; 5217.01,3798.23 5217.01,3812.16 ; 5221.13,3822.09 ccw(c5231.06,3812.16) 5217.01,3812.16 ; v3@5225.05,3835.02 cw(c5207.01,3833.44) 5220.88,3821.8 cw(c5234.75,3810.16) v3@5233.17,3828.2
  MidLayer2 w4: v1@4940.19,1575.54 cw(c4940.19,1552.61) 4956.41,1568.82 cw(c4972.63,1585.04) v1@4949.69,1585.04 ; v1@4940.19,1579.54 cw(c4940.19,1566.26) 4949.58,1575.65 cw(c4958.97,1585.04) v1@4945.69,1585.04 ; v1(4940.19,1585.04) 5000.19,1525.04 5141.86,1383.37 5275.9,1383.37 5425.9,1233.37 5564.18,1233.37 5584.09,1253.29 5686.95,1253.29 5724.02,1216.21 5894.69,1216.21 5919.69,1241.21 6039.05,1241.21 6125.25,1155 6138.52,1155 6148.52,1145 6148.52,983.37 6190.19,941.71 6458.29,941.71 6691.77,708.23 6691.77,648.46 v1(6990.19,350.04) ; v1@6980.69,350.04 ccw(c6957.76,350.04) 6973.97,366.26 ccw(c6990.19,382.48) v1@6990.19,359.54 ; v1@6984.69,350.04 ccw(c6971.41,350.04) 6980.8,359.43 ccw(c6990.19,368.82) v1@6990.19,355.54
  Bottom Layer w4: R241.1@5061.18,2439.55 5061.18,2441.71 5099.19,2441.71 v1(5107.52,2433.37) ; R241.1@5064.47,2441.71 cw(c5064.47,2390.32) v1@5100.81,2426.66 ; R241.1@5064.94,2436.28 cw(c5078.06,2423.16) 5078.06,2441.71 ; R241.1@5067.77,2433.45 cw(c5087.71,2413.51) 5087.71,2441.71 ; R241.1@5067.77,2446.63 ccw(c5079.65,2458.5) 5079.65,2441.71 ; 5074.13,2441.71 cw(c5074.13,2399.98) v1@5103.64,2429.49 ; 5083.79,2441.71 cw(c5083.79,2409.64) v1@5106.46,2432.31 ; 5093.44,2441.71 cw(c5093.44,2419.29) v1@5109.29,2435.14
DIPSW.D3: R240.1 SW8.13 U8.AD9 | length 5990.6
  Top Layer w4: 5095,2342.25 5148,2289.25 5148,2038.18 5143.19,2033.37 5123.52,2013.71 5123.52,1447.06 5114.86,1438.39 5114.86,1275.37 v1(5131.86,1258.37) ; 5100,2337.25 5090.02,2347.23 5090.02,2450.02 5100,2460 v1(5140,2460) 5140,2522.5 5162.5,2545 5162.5,2597.02 5131.69,2627.83 5131.69,2652.27 5110.5,2673.46 5110.5,2756.79 5092.09,2775.21 ; v1@5122.36,1258.37 ccw(c5099.42,1258.37) 5115.64,1274.59 ccw(c5131.86,1290.81) v1@5131.86,1267.87 ; v1@5126.36,1258.37 ccw(c5113.08,1258.37) 5122.47,1267.76 ccw(c5131.86,1277.15) v1@5131.86,1263.87 ; v1@5133.28,2453.28 ccw(c5117.06,2437.06) 5117.06,2460 ccw(c5117.06,2482.93) 5133.28,2466.72 ccw(c5117.06,2482.93) 5140,2482.93 ccw(c5162.93,2482.93) v1@5146.72,2466.72 ; v1@5136.11,2456.11 ccw(c5126.72,2446.72) 5126.72,2460 ccw(c5126.72,2473.28) 5136.11,2463.89 ccw(c5126.72,2473.28) 5140,2473.28 ccw(c5153.28,2473.28) v1@5143.89,2463.89 ; 5156.86,3488.04 5152.19,3483.37 ; U8.AD9@5205.49,3776.61 cw(c5187.77,3776.61) 5200.3,3764.08 ; U8.AD9@5212.83,3769.27 ccw(c5212.83,3751.55) 5200.3,3764.08 ; SW8.13@7090,414.29 7090,408.37 7115.19,408.37 ; SW8.13@7107.4,403.94 cw(c7115.19,399.31) 7115.19,408.37 ; v1@7122.36,425.04 cw(c7099.42,425.04) 7115.64,408.82 cw(c7131.86,392.61) v1@7131.86,415.54 ; v1@7126.36,425.04 cw(c7113.08,425.04) 7122.47,415.65 cw(c7131.86,406.26) v1@7131.86,419.54 ; v1(7131.86,425.04) 7115.19,408.37 ; 5084.31,2782.87 4998.52,2868.66 4998.52,2958.02 4973.52,2983.02 4973.52,3122.06 5039.19,3187.73 5039.19,3219.71 5050.19,3230.71 5062.52,3230.71 5110.86,3279.04 5110.86,3416.71 5090.19,3437.37 5090.19,3458.37 5115.19,3483.37 5152.19,3483.37 ; 5084.31,2782.87 5091.98,2775.21 5092.09,2775.21 ; 5084.31,2782.87 5084.42,2782.87 5092.09,2775.21 ; 5152.19,3483.37 5190.02,3521.21 5190.02,3570.54 5185.02,3575.54 5185.02,3616.54 5188.97,3620.49 5188.97,3660 5188.97,3670 5188.97,3672.79 5188.97,3736.73 cw(c5227.65,3736.73) 5200.3,3764.08
  Bottom Layer w4: R240.1@5061.18,2495.45 5104.55,2495.45 v1(5140,2460) ; R240.1@5064.94,2491.69 cw(c5074.02,2482.61) 5074.02,2495.45 cw(c5074.02,2508.3) R240.1@5064.94,2499.22 ; R240.1@5067.77,2488.86 cw(c5083.68,2472.96) 5083.68,2495.45 cw(c5083.68,2517.95) R240.1@5067.77,2502.04 ; v1@5130.5,2460 ccw(c5107.56,2460) 5123.78,2476.22 ccw(c5140,2492.43) v1@5140,2469.5 ; v1(5131.86,1258.37) 5165,1258.37 5182,1275.37 5472.58,1275.37 5489.58,1258.37 5646.96,1101 5780.29,1101 5842.29,1039 5909.94,1039 6007.23,941.71 6472.8,941.71 6498.13,967.04 6797.96,967.04 7040,725 7040,516.9 v1(7131.86,425.04) ; v1@5134.5,2460 ccw(c5121.22,2460) 5130.61,2469.39 ccw(c5140,2478.78) v1@5140,2465.5 ; v1@5135.75,1254.49 cw(c5145.14,1245.1) 5145.14,1258.37 cw(c5145.14,1271.65) v1@5135.75,1262.26 ; v1@5138.57,1251.66 cw(c5154.79,1235.44) 5154.79,1258.37 cw(c5154.79,1281.31) v1@5138.57,1265.09 ; v1@7122.36,425.04 ccw(c7099.42,425.04) 7115.64,441.26 ccw(c7131.86,457.48) v1@7131.86,434.54 ; v1@7126.36,425.04 ccw(c7113.08,425.04) 7122.47,434.43 ccw(c7131.86,443.82) v1@7131.86,430.54
DIPSW.D4: R239.1 SW8.12 U8.AF7 | length 6536.2
  Top Layer w4: v1@4953.28,2536.72 ccw(c4937.06,2552.93) 4960,2552.93 ccw(c4982.93,2552.93) v1@4966.72,2536.72 ; v1@4956.11,2533.89 ccw(c4946.72,2543.28) 4960,2543.28 ccw(c4973.28,2543.28) v1@4963.89,2533.89 ; v1(4960,2530) 4960,2605 4974.02,2619.02 4974.02,2655.98 4937.5,2692.5 4937.5,2735.64 4981.86,2780 4981.86,2950.04 4956.86,2975.04 4956.86,3132.71 4981.86,3157.71 4981.86,3195.37 v1(5053.19,3266.71) ; v1@5043.69,3266.71 cw(c5020.76,3266.71) 5036.97,3250.49 cw(c5053.19,3234.27) v1@5053.19,3257.21 ; v1@5047.69,3266.71 cw(c5034.41,3266.71) 5043.8,3257.32 cw(c5053.19,3247.93) v1@5053.19,3261.21 ; v1(5123.86,3554.37) 5134.09,3564.61 5134.09,3655.26 5134.09,3660 5134.09,3670 U8.AF7@5134.09,3697.87 ; U8.AF7@5128.79,3692.57 cw(c5115.99,3679.77) 5134.09,3679.77 cw(c5152.2,3679.77) U8.AF7@5139.4,3692.57 ; v1@7165.19,490.54 cw(c7165.19,467.61) 7181.41,483.82 cw(c7197.63,500.04) v1@7174.69,500.04 ; v1@7165.19,494.54 cw(c7165.19,481.26) 7174.58,490.65 cw(c7183.97,500.04) v1@7170.69,500.04 ; v1(7165.19,500.04) 7190.19,475.04 ; SW8.12@7180.07,457.72 ccw(c7170.31,475.04) 7190.19,475.04 ; SW8.12@7182.03,454.23 ccw(c7174.16,468.2) 7190.19,468.2 ; SW8.12@7190,414.29 7190,440.08 7190.19,440.08 7190.19,475.04 ; 7190.19,468.07 ccw(c7206.37,468.07) SW8.12@7198.2,454.1 ; SW8.12@7200.22,457.55 cw(c7210.45,475.04) 7190.19,475.04 ; 5134.09,3680.15 ccw(c5116.37,3680.15) 5128.9,3692.68 cw(c5116.37,3680.15) 5134.09,3680.15 ; 5134.09,3680.15 cw(c5151.82,3680.15) 5139.29,3692.68 ccw(c5151.82,3680.15) 5134.09,3680.15
  MidLayer1 w4: v1@4960,2520.5 cw(c4960,2497.56) 4976.22,2513.78 cw(c4992.43,2530) v1@4969.5,2530 ; v1@4960,2524.5 cw(c4960,2511.22) 4969.39,2520.61 cw(c4978.78,2530) v1@4965.5,2530 ; v1@4960,2529.16 v1(4960,2530) 4990,2500 4990,2441.52 4940.19,2391.71 4940.19,2366.71 4817.47,2243.99 4731.19,2157.71 4731.19,1970.15 4732.34,1969 4732.34,1941 4731.19,1939.85 4731.19,1348.34 5211.53,868 6082,868 6297.69,652.31 6297.69,500 6362.69,435 6475.15,435 6540.19,500.04 v1(7165.19,500.04) ; v1@7158.47,493.32 ccw(c7142.26,477.11) 7142.26,500.04 ccw(c7142.26,522.98) v1@7158.47,506.76 ; v1@7161.3,496.15 ccw(c7151.91,486.76) 7151.91,500.04 ccw(c7151.91,513.32) v1@7161.3,503.93
  MidLayer2 w4: v1@5043.69,3266.71 ccw(c5020.76,3266.71) 5036.97,3282.93 ccw(c5053.19,3299.14) v1@5053.19,3276.21 ; v1@5047.69,3266.71 ccw(c5034.41,3266.71) 5043.8,3276.1 ccw(c5053.19,3285.49) v1@5053.19,3272.21 ; v1(5053.19,3266.71) 5015.19,3304.71 5015.19,3341.37 5023.52,3349.71 5124.52,3349.71 5140.19,3365.37 5140.19,3477.71 5106.86,3511.04 5106.86,3537.37 v1(5123.86,3554.37) ; v1@5114.36,3554.37 cw(c5091.42,3554.37) 5107.64,3538.16 cw(c5123.86,3521.94) v1@5123.86,3544.87 ; v1@5118.36,3554.37 cw(c5105.08,3554.37) 5114.47,3544.99 cw(c5123.86,3535.6) v1@5123.86,3548.87
  Bottom Layer w4: v1(4960,2530) 4964.96,2525.04 5047.85,2525.04 5061.18,2538.37 R239.1@5061.18,2551.36 ; v1@4961.06,2531.06 ccw(c4975.59,2545.59) 4975.59,2525.04 ; v1@4963.89,2533.89 ccw(c4985.25,2555.25) 4985.25,2525.04 ; v1@4966.72,2523.28 cw(c4970.96,2519.04) 4970.96,2525.04 ; v1@4966.72,2536.72 ccw(c4994.91,2564.91) 4994.91,2525.04 ; 5054.1,2531.29 ccw(c5047.34,2538.04) R239.1@5054.35,2544.54 ; 5057.03,2534.23 ccw(c5050.39,2540.87) R239.1@5057.28,2547.26 ; 5059.97,2537.16 ccw(c5053.44,2543.7) R239.1@5060.21,2549.97
DIPSW.D5: R238.1 SW8.11 U8.AA9 | length 5936.8
  Top Layer w4: v3(5193.15,3875.04) U8.AA9@5212.83,3894.72 ; U8.AA9@5205.33,3894.72 cw(c5187.23,3894.72) 5200.03,3881.92 cw(c5212.83,3869.12) U8.AA9@5212.83,3887.22 ; U8.AA9@5205.49,3894.72 cw(c5187.77,3894.72) 5200.3,3882.19 cw(c5212.83,3869.66) U8.AA9@5212.83,3887.38 ; v1(6759.19,608.37) 7106.63,608.37 7223,492 7278,492 7290,480 SW8.11@7290,414.29 ; v1@6763.08,604.49 cw(c6772.47,595.1) 6772.47,608.37 cw(c6772.47,621.65) v1@6763.08,612.26 ; v1@6765.91,601.66 cw(c6782.13,585.44) 6782.13,608.37 cw(c6782.13,631.31) v1@6765.91,615.09 ; SW8.11@7278.04,456.41 ccw(c7260.76,480) 7290,480 ccw(c7319.24,480) SW8.11@7301.96,456.41 ; SW8.11@7280.4,453.18 ccw(c7266.54,472.11) 7290,472.11 ccw(c7313.46,472.11) SW8.11@7299.6,453.18 ; SW8.11@7282.77,449.96 ccw(c7272.32,464.22) 7290,464.22 ccw(c7307.68,464.22) SW8.11@7297.23,449.96 ; 5205.95,3887.84 cw(c5193.15,3900.65) 5193.15,3882.54 ccw(c5193.15,3900.65) 5205.95,3887.84 ; 5205.95,3887.84 ccw(c5218.76,3875.04) 5200.65,3875.04 cw(c5218.76,3875.04) 5205.95,3887.84
  MidLayer1 w4: v1(5105,2630) 5109.82,2630 5123.52,2643.71 ; v1@5106.33,2635.34 ccw(c5109.45,2647.79) 5118.53,2638.71 ; v1@5107.31,2639.22 ccw(c5111.45,2655.78) 5123.52,2643.71 ; v1@5114.5,2630 cw(c5125.81,2630) 5117.81,2638 ; 5169.29,3798.23 5169.29,3812.16 ; v3@5185.68,3874.39 cw(c5167.64,3872.81) 5181.51,3861.17 ; v3@5193.8,3867.57 ccw(c5195.38,3849.53) 5181.51,3861.17 ; v1@5383.52,2480.54 cw(c5383.52,2457.61) 5399.74,2473.82 cw(c5415.96,2490.04) v1@5393.02,2490.04 ; v1@5383.52,2484.54 cw(c5383.52,2471.26) 5392.91,2480.65 cw(c5402.3,2490.04) v1@5389.02,2490.04 ; v1(5383.52,2490.04) 5401.52,2472.04 5401.52,2425 5407.19,2419.33 5407.19,1326.18 5500,1233.37 5873.52,1233.37 6498.52,608.37 v1(6759.19,608.37) ; v1@6752.47,601.66 ccw(c6736.26,585.44) 6736.26,608.37 ccw(c6736.26,631.31) v1@6752.47,615.09 ; v1@6755.3,604.49 ccw(c6745.91,595.1) 6745.91,608.37 ccw(c6745.91,621.65) v1@6755.3,612.26 ; 5123.52,2643.71 5123.52,2738.73 5031.86,2830.39 5031.86,3110.67 5081.19,3160 5081.19,3234.04 5106.5,3259.35 5106.5,3349.68 5106.86,3350.04 5140.19,3383.37 5148.86,3392.04 5148.86,3489.67 5176.52,3517.34 5176.52,3577.71 5169.29,3584.94 5169.29,3660 5169.29,3670 5169.29,3718.62 5169.29,3738.04 5169.29,3812.16 ; 5169.29,3812.16 5169.29,3831.66 cw(c5211.02,3831.66) 5181.51,3861.17
  Bottom Layer w4: R238.1@5061.18,2607.27 5061.18,2608.37 5088.19,2608.37 5107.41,2627.59 v1@5109.82,2630 ; R238.1@5064.94,2604 cw(c5075.5,2593.45) 5075.5,2608.37 ; R238.1@5064.94,2611.53 ccw(c5072.55,2619.13) 5072.55,2608.37 ; R238.1@5067.77,2601.17 cw(c5085.15,2583.79) 5085.15,2608.37 ; R238.1@5067.77,2614.35 ccw(c5082.2,2628.79) 5082.2,2608.37 ; 5090.6,2610.78 ccw(c5077.27,2624.11) v1@5095.71,2628.03 ; 5095.81,2615.99 ccw(c5085.87,2625.94) v1@5099.62,2628.86 ; 5097,2617.19 cw(c5105,2609.19) v1@5105,2620.5 ; v1(5105,2630) v1@5109.82,2630 ; v1@5105.22,2628.52 cw(c5107.83,2610.93) 5120.4,2623.5 ; v1@5105.81,2624.56 cw(c5109.28,2601.14) 5126.02,2617.88 ; v1@5374.02,2490.04 ccw(c5351.09,2490.04) 5367.31,2506.26 ccw(c5383.52,2522.48) v1@5383.52,2499.54 ; v1@5378.02,2490.04 ccw(c5364.75,2490.04) 5374.14,2499.43 ccw(c5383.52,2508.82) v1@5383.52,2495.54 ; v1(5383.52,2490.04) 5256.86,2616.71 5127.19,2616.71 v1@5111.86,2632.04 ; v1@5109.82,2630 v1@5111.86,2632.04 ; v1@5109.82,2630 v1@5111.86,2632.04
DIPSW.D6: R237.1 SW8.10 U8.AC7 | length 6305.4
  Top Layer w4: v3(5114.41,3796.3) U8.AC7@5134.09,3815.98 ; U8.AC7@5126.59,3815.98 cw(c5108.49,3815.98) 5121.29,3803.18 cw(c5134.09,3790.38) U8.AC7@5134.09,3808.48 ; U8.AC7@5126.75,3815.98 cw(c5109.03,3815.98) 5121.56,3803.45 cw(c5134.09,3790.92) U8.AC7@5134.09,3808.64 ; v1@6731.86,690.54 cw(c6731.86,667.61) 6748.07,683.82 cw(c6764.29,700.04) v1@6741.36,700.04 ; v1@6731.86,694.54 cw(c6731.86,681.26) 6741.25,690.65 cw(c6750.64,700.04) v1@6737.36,700.04 ; v1(6731.86,700.04) 6811.9,620 7110,620 7230,500 7370,500 7390,480 ; SW8.10@7378.04,456.41 ccw(c7360.78,479.99) 7390,479.99 ; SW8.10@7380.41,453.19 ccw(c7366.55,472.11) 7390,472.11 ccw(c7413.46,472.11) SW8.10@7399.6,453.18 ; SW8.10@7382.77,449.96 ccw(c7372.33,464.22) 7390,464.22 ccw(c7407.68,464.22) SW8.10@7397.24,449.96 ; SW8.10@7390,414.29 7390,416.71 7390,480 ; SW8.10@7401.96,456.41 cw(c7419.24,479.99) 7390,479.99 ; 5127.21,3809.1 cw(c5114.41,3821.91) 5114.41,3803.8 ccw(c5114.41,3821.91) 5127.21,3809.1 ; 5127.21,3809.1 ccw(c5140.02,3796.3) 5121.91,3796.3 cw(c5140.02,3796.3) 5127.21,3809.1
  MidLayer1 w4: v1@5075.5,2695 ccw(c5052.56,2695) 5068.78,2711.22 ccw(c5085,2727.43) v1@5085,2704.5 ; v1@5079.5,2695 ccw(c5066.22,2695) 5075.61,2704.39 ccw(c5085,2713.78) v1@5085,2700.5 ; v1(5085,2695) 5060,2720 5060,2724.88 4981.86,2803.02 4981.86,3149.35 4989.19,3156.69 4989.19,3376.75 5040.94,3428.5 5082.98,3428.5 5096.19,3441.71 5096.19,3572.71 5114.41,3590.93 5114.41,3660 5114.41,3670 5114.41,3718.62 v3(5114.41,3796.3) ; v3@5109.22,3791.11 cw(c5096.68,3778.57) 5114.41,3778.57 cw(c5132.14,3778.57) v3@5119.6,3791.11 ; v1(5485.19,2221.71) 5473.52,2210.04 5473.52,1736.71 6085.19,1125.04 6510.19,700.04 v1(6731.86,700.04) ; v1@6725.14,693.32 ccw(c6708.92,677.11) 6708.92,700.04 ccw(c6708.92,722.98) v1@6725.14,706.76 ; v1@6727.97,696.15 ccw(c6718.58,686.76) 6718.58,700.04 ccw(c6718.58,713.32) v1@6727.97,703.93 ; 5114.41,3778.19 cw(c5132.52,3778.19) 5119.71,3791 ccw(c5132.52,3778.19) 5114.41,3778.19 ; 5114.41,3778.19 ccw(c5096.3,3778.19) 5109.11,3791 cw(c5096.3,3778.19) 5114.41,3778.19
  Bottom Layer w4: 5044.43,2646.43 cw(c5061.18,2629.68) R237.1@5061.18,2653.37 ; 5045.62,2647.62 ccw(c5030.55,2662.69) R237.1@5051.86,2662.69 ; R237.1@5051.26,2653.26 cw(c5061.18,2643.34) R237.1@5061.18,2657.37 ; R237.1@5052.45,2654.45 ccw(c5044.21,2662.69) R237.1@5055.86,2662.69 ; R237.1@5065,2659.48 cw(c5073.74,2651.02) 5073.74,2663.18 cw(c5073.74,2675.34) R237.1@5065,2666.88 ; R237.1@5067.88,2656.7 cw(c5083.18,2641.87) 5083.18,2663.18 ; R237.1@5067.88,2669.66 ccw(c5083.18,2684.49) 5083.18,2663.18 ; v1@5078.28,2688.28 cw(c5062.06,2672.06) 5085,2672.06 cw(c5107.93,2672.06) v1@5091.72,2688.28 ; v1@5081.11,2691.11 cw(c5071.72,2681.72) 5085,2681.72 cw(c5098.28,2681.72) v1@5088.89,2691.11 ; v1(5085,2695) 5085,2665 5083.18,2663.18 ; v1@5485.19,2212.21 cw(c5485.19,2189.27) 5501.41,2205.49 cw(c5517.63,2221.71) v1@5494.69,2221.71 ; v1@5485.19,2216.21 cw(c5485.19,2202.93) 5494.58,2212.32 cw(c5503.97,2221.71) v1@5490.69,2221.71 ; v1(5485.19,2221.71) 5515.19,2191.71 5548.52,2191.71 5565.19,2175.04 5565.19,2091.71 5556.86,2083.37 5231.86,2083.37 5206.86,2108.37 5206.86,2441.71 5223.52,2458.37 5223.52,2525.04 5148.52,2600.04 5139.19,2600.04 5122.52,2583.37 5048.52,2583.37 5040.19,2591.71 5040.19,2642.19 R237.1@5061.18,2663.18 5083.18,2663.18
